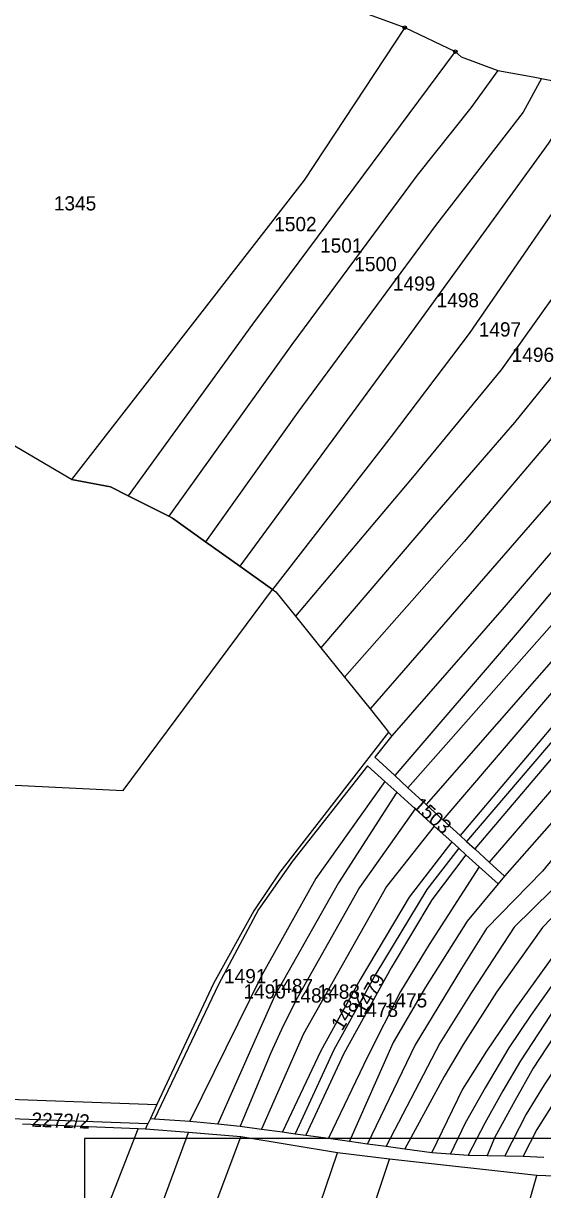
# Model space of a CAD drawing. Extents: x -564516 to -563466, y -1163913 to -1163170.
# Drawn here: x -563898.7 to -563752.8, y -1163661.7 to -1163334.3 of the extents above; entities that cross this region are included whole.
import ezdxf

# ---------------------------------------------------------------- set-up
doc = ezdxf.new("R2010")
doc.units = 0
for name, color, linetype in [('_Rám HC11-R', 7, 'Continuous'), ('Hranice parcel', 7, 'Continuous'), ('Obvod PU', 7, 'Continuous'), ('Parcelní čísla', 7, 'Continuous'), ('Značky bodu BP', 7, 'Continuous')]:
    doc.layers.add(name, color=color, linetype=linetype)

msp = doc.modelspace()

# ---------------------------------------------------------------- linework, layer by layer
at = {"layer": '_Rám HC11-R'}
for p, q in [((-563466.35, -1163647.3), (-563881.49, -1163647.3)), ((-563881.49, -1163647.3), (-563881.49, -1163733.08))]:
    msp.add_line(p, q, dxfattribs=at)
at = {"layer": 'Hranice parcel'}
for p, q in [((-563857.82, -1163472.67), (-563869.21, -1163466.93)), ((-563837.86, -1163486.67), (-563847.48, -1163479.82)), ((-563828.67, -1163493.21), (-563837.86, -1163486.67)), ((-563796.11, -1163533.24), (-563795.18, -1163534.26)), ((-563794.33, -1163545.44), (-563790.62, -1163548.85)), ((-563793.75, -1163550.13), (-563797.12, -1163547.09)), ((-563790.62, -1163548.85), (-563785.48, -1163553.57)), ((-563788.65, -1163554.75), (-563793.75, -1163550.13)), ((-563783.29, -1163559.6), (-563788.65, -1163554.75)), ((-563785.48, -1163553.57), (-563780.79, -1163557.87)), ((-563778.33, -1163564.08), (-563783.29, -1163559.6)), ((-563780.79, -1163557.87), (-563775.97, -1163562.3)), ((-563775.97, -1163562.3), (-563774.21, -1163563.92)), ((-563776.36, -1163565.86), (-563778.33, -1163564.08)), ((-563774.37, -1163567.65), (-563776.36, -1163565.86)), ((-563774.21, -1163563.92), (-563771.89, -1163566.05)), ((-563771.89, -1163566.05), (-563767.85, -1163569.76)), ((-563770.6, -1163571.06), (-563774.37, -1163567.65)), ((-563765.33, -1163575.83), (-563770.6, -1163571.06)), ((-563767.85, -1163569.76), (-563763.55, -1163573.71)), ((-563763.55, -1163573.71), (-563765.33, -1163575.83)), ((-563862.98, -1163641.72), (-563861.79, -1163641.8)), ((-563866.43, -1163644.59), (-563898.88, -1163643.25)), ((-563864.35, -1163644.68), (-563866.43, -1163644.59)), ((-563864.35, -1163644.68), (-563863.67, -1163643.2)), ((-563852.28, -1163645.65), (-563864.35, -1163644.68)), ((-563861.79, -1163641.8), (-563851.85, -1163642.43)), ((-563851.85, -1163642.43), (-563844.04, -1163643.21)), ((-563844.04, -1163643.21), (-563837.73, -1163643.84)), ((-563837.73, -1163643.84), (-563831.77, -1163644.66)), ((-563831.77, -1163644.66), (-563825.88, -1163645.47)), ((-563837.56, -1163646.83), (-563852.28, -1163645.65)), ((-563810.46, -1163651.3), (-563837.56, -1163646.83)), ((-563825.88, -1163645.47), (-563822.3, -1163645.97)), ((-563822.3, -1163645.97), (-563819.33, -1163646.38)), ((-563819.33, -1163646.38), (-563812.92, -1163647.26)), ((-563812.92, -1163647.26), (-563807, -1163648.08)), ((-563807, -1163648.08), (-563801.98, -1163648.77)), ((-563795.8, -1163653.08), (-563810.46, -1163651.3)), ((-563801.98, -1163648.77), (-563796.78, -1163649.49)), ((-563796.78, -1163649.49), (-563791.48, -1163650.22)), ((-563791.48, -1163650.22), (-563783.88, -1163651.27)), ((-563783.88, -1163651.27), (-563778.72, -1163651.64)), ((-563754.39, -1163657.71), (-563795.8, -1163653.08)), ((-563778.72, -1163651.64), (-563773.69, -1163652.01)), ((-563773.69, -1163652.01), (-563768.37, -1163652.1)), ((-563768.37, -1163652.1), (-563763.4, -1163652.18)), ((-563763.4, -1163652.18), (-563758.25, -1163652.26)), ((-563758.25, -1163652.26), (-563752.45, -1163652.53))]:
    msp.add_line(p, q, dxfattribs=at)
for points in [[(-563897.93, -1163321.91), (-563881.27, -1163324.26), (-563870.72, -1163325.36), (-563853.83, -1163325.33), (-563836.35, -1163326.49), (-563819.97, -1163326.37), (-563805.63, -1163330.27), (-563791.55, -1163335.5)], [(-563472.82, -1163325.1), (-563492.4, -1163344.19), (-563563.12, -1163409.18), (-563578.9, -1163425.55), (-563599.71, -1163447.94), (-563619.51, -1163469.95), (-563641.92, -1163497.36), (-563657.79, -1163516.57), (-563674.09, -1163534.63), (-563706.73, -1163569.48), (-563730.65, -1163592.66), (-563738.15, -1163601.56), (-563747.8, -1163615.9), (-563755.42, -1163627.59), (-563760.64, -1163636.71), (-563766.24, -1163646.94), (-563768.37, -1163652.1)], [(-563466.35, -1163326.54), (-563481.91, -1163341.79), (-563503.39, -1163361.7), (-563547.11, -1163402.34), (-563568.21, -1163422.97), (-563585.7, -1163441.32), (-563598.54, -1163455.13), (-563615.18, -1163473.64), (-563641.36, -1163506.22), (-563651.94, -1163518.83), (-563666.9, -1163535.69), (-563692.99, -1163562.42), (-563722.34, -1163590.39), (-563729.59, -1163598.52), (-563734.31, -1163604.94), (-563752.39, -1163632.21), (-563757.45, -1163640.46), (-563763.4, -1163652.18)], [(-563483.32, -1163328.82), (-563498.3, -1163343.11), (-563559.5, -1163398.24), (-563581.3, -1163420.87), (-563602.34, -1163443.09), (-563626.81, -1163470.77), (-563647.88, -1163496.75), (-563660.04, -1163511.31), (-563676.05, -1163529.51), (-563701.44, -1163556.83), (-563716.72, -1163573.04), (-563732.31, -1163588.43), (-563737.4, -1163593.77), (-563742.55, -1163600.35), (-563759.04, -1163625.53), (-563764.01, -1163633.9), (-563769.07, -1163642.98), (-563773.69, -1163652.01)], [(-563492.6, -1163332.11), (-563503.83, -1163342.23), (-563543.19, -1163374.77), (-563566.39, -1163396.02), (-563581.06, -1163411.4), (-563611.4, -1163444.26), (-563633.36, -1163469.72), (-563656.32, -1163498.04), (-563671.96, -1163517.15), (-563698.7, -1163546.56), (-563722.03, -1163572.73), (-563739.26, -1163589.69), (-563745.02, -1163596.95), (-563756.14, -1163612.7), (-563762.32, -1163621.9), (-563768.98, -1163633.06), (-563774.53, -1163643.02), (-563778.72, -1163651.64)], [(-563466.35, -1163334.65), (-563469.98, -1163338.28), (-563528.11, -1163391.43), (-563558.62, -1163421.51), (-563591.76, -1163455.37), (-563604.54, -1163469.78), (-563623.3, -1163492.1), (-563640.43, -1163514.2), (-563664.39, -1163540.31), (-563688.43, -1163564.48), (-563715.35, -1163589.39), (-563722.97, -1163598.27), (-563730.84, -1163608.39), (-563744.99, -1163629.78), (-563754.42, -1163644.83), (-563758.25, -1163652.26)], [(-563777.33, -1163342.23), (-563834.3, -1163418.69), (-563869.21, -1163466.93)], [(-563765.35, -1163347.57), (-563773, -1163358.05), (-563788.06, -1163376.95), (-563823.25, -1163424.41), (-563857.82, -1163472.67)], [(-563753.13, -1163349.77), (-563758.23, -1163359.19), (-563782.92, -1163391.06), (-563821.57, -1163443.45), (-563847.48, -1163479.82)], [(-563741.17, -1163352.18), (-563751.2, -1163367.9), (-563792.39, -1163424.69), (-563837.86, -1163486.67)], [(-563713.76, -1163353.55), (-563720.43, -1163365.52), (-563729.77, -1163380.88), (-563746.85, -1163406.86), (-563764.48, -1163431.56), (-563789.31, -1163461.75), (-563822.23, -1163500.72)], [(-563728.29, -1163354.11), (-563737.56, -1163369.29), (-563773.44, -1163421.36), (-563795.34, -1163450.25), (-563828.67, -1163493.21)], [(-563699.78, -1163358.19), (-563728.89, -1163404.04), (-563737.32, -1163416.29), (-563747.58, -1163430.19), (-563760.69, -1163446.32), (-563783.69, -1163472.87), (-563815.06, -1163509.62)], [(-563543.33, -1163366.56), (-563560.24, -1163380.59), (-563575.51, -1163395.61), (-563587.9, -1163408.53), (-563615.49, -1163438.94), (-563638.39, -1163465.51), (-563662.96, -1163496.57), (-563671.73, -1163507.71), (-563679.68, -1163517.09), (-563727.09, -1163571.29), (-563745.65, -1163590.22), (-563760.54, -1163610.94), (-563768.6, -1163622.84), (-563775.35, -1163633.43), (-563783.88, -1163651.27)], [(-563689.86, -1163366.77), (-563715.18, -1163405.25), (-563725.97, -1163420.3), (-563736.24, -1163434), (-563748.18, -1163448.29), (-563774.88, -1163479.69), (-563808.46, -1163517.81)], [(-563679.27, -1163371.76), (-563694.05, -1163396.08), (-563712.48, -1163422.43), (-563720.92, -1163433.15), (-563739.42, -1163455.73), (-563801.27, -1163526.74)], [(-563667.47, -1163374.34), (-563677.18, -1163389.79), (-563698.38, -1163420.64), (-563711.4, -1163437.22), (-563763.65, -1163498.18), (-563795.18, -1163534.26)], [(-563658.96, -1163375.96), (-563669.76, -1163391.76), (-563692.1, -1163423.75), (-563705.37, -1163440.46), (-563718.89, -1163456.66), (-563758.83, -1163504.07), (-563794.33, -1163545.44)], [(-563570.63, -1163375.65), (-563591.87, -1163401.05), (-563652.35, -1163472), (-563669.45, -1163492.8), (-563678.65, -1163504.64), (-563687.04, -1163514.28), (-563717.12, -1163548.46), (-563735.84, -1163570.42), (-563752.86, -1163588.07), (-563765.79, -1163606.25), (-563775.1, -1163620.9), (-563780.5, -1163629.87), (-563791.48, -1163650.22)], [(-563651.05, -1163375.37), (-563656.34, -1163384.04), (-563664.44, -1163396.46), (-563675.61, -1163412.85), (-563686.32, -1163426.87), (-563699.84, -1163443.7), (-563721.69, -1163469.92), (-563749.44, -1163502.25), (-563790.62, -1163548.85)], [(-563643.35, -1163375.85), (-563649.72, -1163386.1), (-563657.97, -1163398.42), (-563666.98, -1163411.37), (-563680.74, -1163429.73), (-563715.73, -1163472.33), (-563744.55, -1163506.78), (-563785.48, -1163553.57)], [(-563635.67, -1163375.6), (-563641.38, -1163386.29), (-563650.68, -1163400.01), (-563658.83, -1163411.7), (-563671.54, -1163427.96), (-563682.13, -1163441.2), (-563736.5, -1163506.06), (-563780.79, -1163557.87)], [(-563626.44, -1163376.19), (-563635.1, -1163389.51), (-563644.02, -1163402.16), (-563654.62, -1163416.74), (-563660.75, -1163424.99), (-563673.26, -1163440.53), (-563692.43, -1163463.56), (-563732.12, -1163510.45), (-563775.97, -1163562.3)], [(-563622.81, -1163376), (-563632.18, -1163390.9), (-563641.24, -1163403.41), (-563652.03, -1163418.46), (-563670.1, -1163441.25), (-563689.49, -1163464.49), (-563728.67, -1163510.67), (-563774.21, -1163563.92)], [(-563618.32, -1163375.77), (-563627.82, -1163390.47), (-563637.79, -1163404.61), (-563650.02, -1163421.29), (-563666.6, -1163442.21), (-563686.47, -1163465.86), (-563726.15, -1163512.25), (-563771.89, -1163566.05)], [(-563610.48, -1163375.86), (-563620.63, -1163391.71), (-563644.93, -1163424.84), (-563658.98, -1163442.31), (-563683.45, -1163471.47), (-563709.83, -1163502.53), (-563767.85, -1163569.76)], [(-563601.82, -1163376.4), (-563613.49, -1163393.34), (-563623.47, -1163407.29), (-563642.11, -1163431.17), (-563652.56, -1163444.37), (-563666.6, -1163461.2), (-563733.58, -1163539.68), (-563763.55, -1163573.71)], [(-563592.53, -1163377), (-563601.56, -1163389.65), (-563617.86, -1163411.46), (-563637.55, -1163436.35), (-563666.96, -1163470.89), (-563697.03, -1163506.74), (-563736.15, -1163551.97), (-563752.86, -1163572.25), (-563768.56, -1163588.36), (-563775.61, -1163599.64), (-563788.58, -1163620.98), (-563801.98, -1163648.77)], [(-563582.12, -1163376.96), (-563599.39, -1163399.12), (-563613.98, -1163417.5), (-563658.26, -1163469.72), (-563679.28, -1163495.13), (-563692.47, -1163510.89), (-563711.44, -1163532.92), (-563744.92, -1163572.34), (-563760.83, -1163588.01), (-563772.79, -1163606.32), (-563781.71, -1163620.54), (-563796.78, -1163649.49)], [(-563885.14, -1163462.32), (-563943.67, -1163427.99), (-563964.47, -1163416.08)], [(-563869.21, -1163466.93), (-563874.2, -1163464.42), (-563885.14, -1163462.32)], [(-563847.48, -1163479.82), (-563856.79, -1163473.19), (-563857.82, -1163472.67)], [(-564028.91, -1163536.42), (-563982.72, -1163544.1), (-563870.61, -1163549.59), (-563828.67, -1163493.21)], [(-563795.18, -1163534.26), (-563799.97, -1163540.26), (-563794.33, -1163545.44)], [(-563797.12, -1163547.09), (-563802.01, -1163542.67), (-563823.04, -1163569.49), (-563832.59, -1163583.01), (-563843.88, -1163604.06), (-563861.79, -1163641.8)], [(-563797.12, -1163547.09), (-563816.52, -1163574.35), (-563831.71, -1163601.49), (-563851.85, -1163642.43)], [(-563793.75, -1163550.13), (-563810.18, -1163575.59), (-563828.05, -1163607.14), (-563844.04, -1163643.21)], [(-563788.65, -1163554.75), (-563804.24, -1163576.88), (-563821.61, -1163607.78), (-563825.67, -1163615.71), (-563829.14, -1163623.28), (-563837.73, -1163643.84)], [(-563783.29, -1163559.6), (-563796.68, -1163576.54), (-563819.98, -1163617.94), (-563831.77, -1163644.66)], [(-563778.33, -1163564.08), (-563790.29, -1163579.56), (-563804.08, -1163602.71), (-563815.08, -1163622.69), (-563825.88, -1163645.47)], [(-563776.36, -1163565.86), (-563785.29, -1163577.43), (-563799.62, -1163601.07), (-563811.41, -1163622.39), (-563822.3, -1163645.97)], [(-563774.37, -1163567.65), (-563783.91, -1163580.3), (-563795.31, -1163599.39), (-563808.64, -1163623.48), (-563819.33, -1163646.38)], [(-563770.6, -1163571.06), (-563784.7, -1163592.88), (-563792.74, -1163606.07), (-563801.96, -1163624.42), (-563812.92, -1163647.26)], [(-563765.33, -1163575.83), (-563774, -1163586.32), (-563785.71, -1163604.79), (-563794.77, -1163620.34), (-563807, -1163648.08)], [(-563945.88, -1163641.11), (-563941.57, -1163637.81), (-563936.63, -1163635.58), (-563931.3, -1163634.54), (-563913.06, -1163635.92), (-563861.14, -1163637.78)], [(-564033.85, -1163887.71), (-563960.37, -1163802.77), (-563924.09, -1163757.23), (-563905.61, -1163729.28), (-563893.92, -1163709.01), (-563880, -1163679.45), (-563866.43, -1163644.59)], [(-564019.41, -1163895.71), (-563980.6, -1163849.7), (-563954.99, -1163819.51), (-563933.77, -1163793.6), (-563915.51, -1163769.54), (-563902.82, -1163750.6), (-563880.21, -1163714.08), (-563865.64, -1163681.81), (-563852.28, -1163645.65)], [(-564005.03, -1163903.67), (-563965.09, -1163855.39), (-563941.49, -1163826.5), (-563923.42, -1163803.62), (-563898.92, -1163768.98), (-563879.88, -1163739.93), (-563867.29, -1163716.65), (-563853.12, -1163688.16), (-563837.56, -1163646.83)], [(-563971.69, -1163912.53), (-563956.92, -1163893.35), (-563932.93, -1163862.62), (-563904.78, -1163824.4), (-563885.89, -1163798.15), (-563869.34, -1163772.9), (-563860.8, -1163759.16), (-563843.13, -1163727.45), (-563830.48, -1163702.96), (-563823.28, -1163687.14), (-563818.58, -1163675.31), (-563810.46, -1163651.3)], [(-563952.94, -1163912.53), (-563942.84, -1163899.5), (-563912.32, -1163858.67), (-563872.16, -1163804.24), (-563858.94, -1163783.59), (-563847.66, -1163765.02), (-563838.38, -1163748.17), (-563818.3, -1163711.53), (-563805.22, -1163681.25), (-563795.8, -1163653.08)], [(-563894.47, -1163912.53), (-563893.96, -1163911.83), (-563855.73, -1163854.72), (-563821.73, -1163800.43), (-563804.05, -1163768.36), (-563784.66, -1163731.46), (-563767.88, -1163695.73), (-563761.87, -1163680.95), (-563757.94, -1163669.74), (-563754.39, -1163657.71)], [(-563719.56, -1163662.87), (-563736.76, -1163658.37), (-563754.39, -1163657.71)]]:
    msp.add_lwpolyline(points, dxfattribs=at)
at = {"layer": 'Obvod PU'}
for p, q in [((-563791.55, -1163335.5), (-563777.33, -1163342.23)), ((-563791.55, -1163335.5), (-563777.33, -1163342.23)), ((-563753.13, -1163349.77), (-563741.17, -1163352.18)), ((-563753.13, -1163349.77), (-563741.17, -1163352.18)), ((-563869.21, -1163466.93), (-563857.82, -1163472.67)), ((-563869.21, -1163466.93), (-563857.82, -1163472.67)), ((-563847.48, -1163479.82), (-563837.86, -1163486.67)), ((-563847.48, -1163479.82), (-563837.86, -1163486.67)), ((-563837.86, -1163486.67), (-563828.67, -1163493.21)), ((-563837.86, -1163486.67), (-563828.67, -1163493.21)), ((-563822.23, -1163500.72), (-563815.06, -1163509.62)), ((-563822.23, -1163500.72), (-563815.06, -1163509.62)), ((-563815.06, -1163509.62), (-563808.46, -1163517.81)), ((-563815.06, -1163509.62), (-563808.46, -1163517.81)), ((-563808.46, -1163517.81), (-563801.27, -1163526.74)), ((-563808.46, -1163517.81), (-563801.27, -1163526.74)), ((-563861.14, -1163637.78), (-563862.98, -1163641.72)), ((-563861.14, -1163637.78), (-563862.98, -1163641.72)), ((-563862.98, -1163641.72), (-563863.67, -1163643.2)), ((-563862.98, -1163641.72), (-563863.67, -1163643.2))]:
    msp.add_line(p, q, dxfattribs=at)
for points in [[(-563791.55, -1163335.5), (-563819.8, -1163378.32), (-563885.14, -1163462.32)], [(-563791.55, -1163335.5), (-563819.8, -1163378.32), (-563885.14, -1163462.32)], [(-563777.33, -1163342.23), (-563775.66, -1163343.66), (-563765.35, -1163347.57)], [(-563777.33, -1163342.23), (-563775.66, -1163343.66), (-563765.35, -1163347.57)], [(-563765.35, -1163347.57), (-563755.49, -1163349.3), (-563753.13, -1163349.77)], [(-563765.35, -1163347.57), (-563755.49, -1163349.3), (-563753.13, -1163349.77)], [(-563885.14, -1163462.32), (-563874.2, -1163464.42), (-563869.21, -1163466.93)], [(-563885.14, -1163462.32), (-563874.2, -1163464.42), (-563869.21, -1163466.93)], [(-563857.82, -1163472.67), (-563856.79, -1163473.19), (-563847.48, -1163479.82)], [(-563857.82, -1163472.67), (-563856.79, -1163473.19), (-563847.48, -1163479.82)], [(-563828.67, -1163493.21), (-563827.74, -1163493.87), (-563822.23, -1163500.72)], [(-563828.67, -1163493.21), (-563827.74, -1163493.87), (-563822.23, -1163500.72)], [(-563801.27, -1163526.74), (-563796.91, -1163532.16), (-563796.11, -1163533.24)], [(-563801.27, -1163526.74), (-563796.91, -1163532.16), (-563796.11, -1163533.24)], [(-563796.11, -1163533.24), (-563826.57, -1163572.54), (-563833.96, -1163583.41), (-563845.27, -1163603.85), (-563861.14, -1163637.78)], [(-563796.11, -1163533.24), (-563826.57, -1163572.54), (-563833.96, -1163583.41), (-563845.27, -1163603.85), (-563861.14, -1163637.78)], [(-563863.67, -1163643.2), (-563930.57, -1163640.78), (-563930.91, -1163641.92)], [(-563863.67, -1163643.2), (-563930.57, -1163640.78), (-563930.91, -1163641.92)]]:
    msp.add_lwpolyline(points, dxfattribs=at)
at = {"layer": 'Značky bodu BP'}
for centre, radius in [((-563791.55, -1163335.5), 0.5), ((-563791.55, -1163335.5), 0.0303), ((-563777.33, -1163342.23), 0.5), ((-563777.33, -1163342.23), 0.0303)]:
    msp.add_circle(centre, radius, dxfattribs=at)

# ---------------------------------------------------------------- texts
at = {"layer": 'Parcelní čísla'}
for s, p in [('1345', (-563890.08, -1163386.81)), ('1502', (-563828.18, -1163392.64)), ('1501', (-563815.3, -1163398.66)), ('1500', (-563805.69, -1163403.86)), ('1499', (-563794.87, -1163409.33)), ('1498', (-563782.59, -1163413.99)), ('1497', (-563770.75, -1163422.2)), ('1496', (-563761.49, -1163429.32)), ('1491', (-563842.28, -1163603.74)), ('1487', (-563829.17, -1163606.52)), ('1490', (-563836.83, -1163608.05)), ('1486', (-563823.8, -1163609.15)), ('1483', (-563816, -1163608.08)), ('1475', (-563797.12, -1163610.53)), ('1478', (-563805.31, -1163613.19))]:
    msp.add_text(s, height=4, dxfattribs=at).set_placement(p)
for s, rotation, p in [('1503', 318, (-563789.53, -1163554.16)), ('1479', 60, (-563802.8, -1163612.79)), ('1482', 57, (-563809.16, -1163617.34)), ('2272/2', 358, (-563896.43, -1163644))]:
    msp.add_text(s, height=4, rotation=rotation, dxfattribs=at).set_placement(p)

doc.saveas('drawing.dxf')
